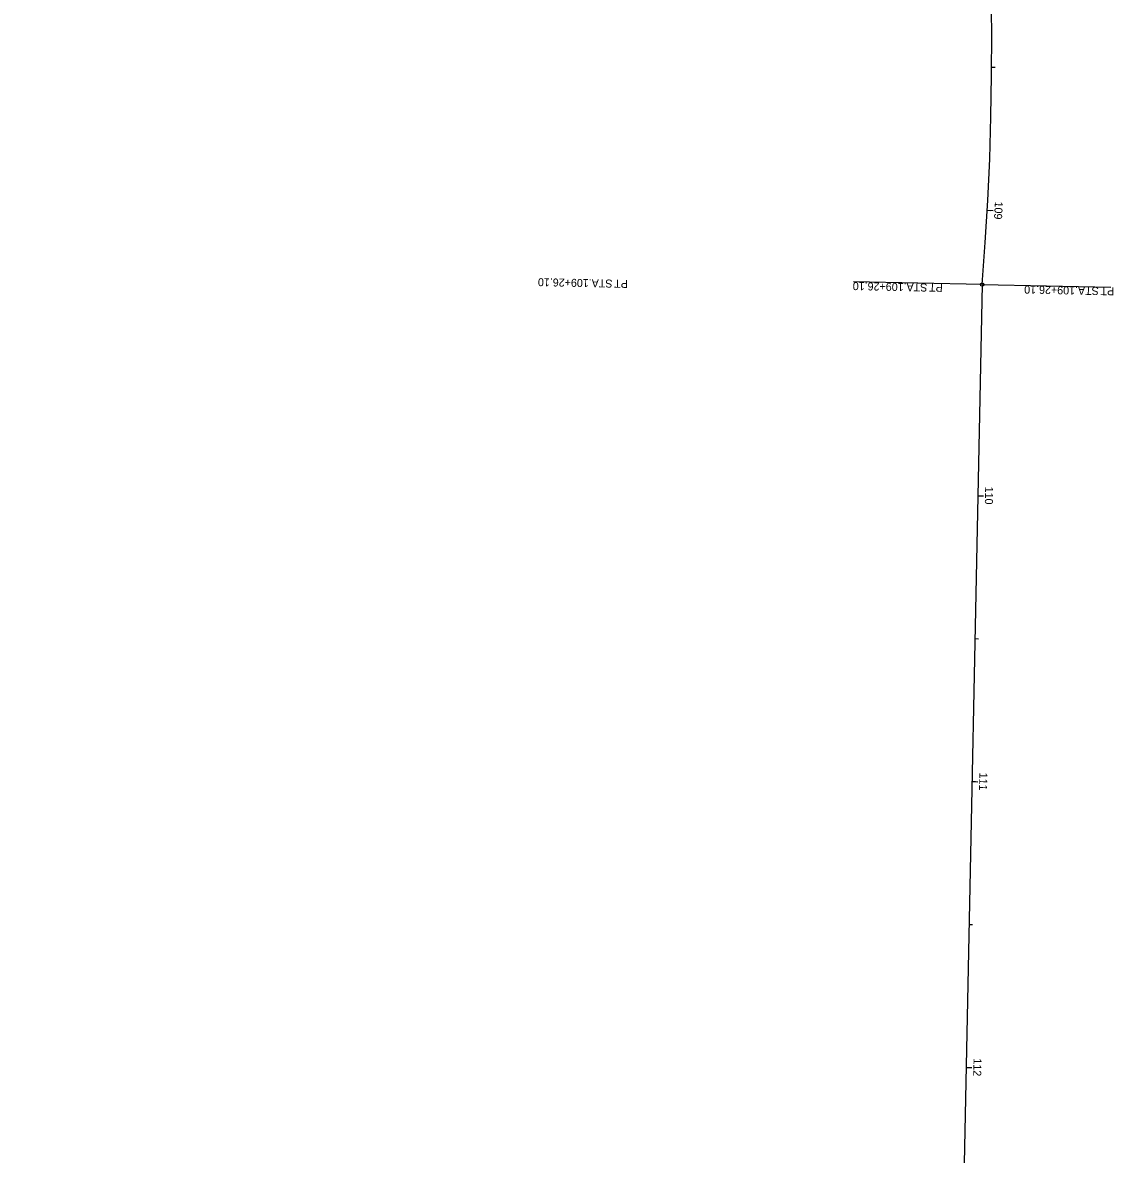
# Model space of a CAD drawing. Extents: x 1392427 to 1392809, y 435950 to 439080.
# Drawn here: x 1392427.6 to 1392809.3, y 437913.4 to 438309.3 of the extents above; entities that cross this region are included whole.
import ezdxf

# ---------------------------------------------------------------- set-up
doc = ezdxf.new("R2010")
doc.units = 0
for name, color, linetype in [('Default', 7, 'Continuous'), ('PV_X_Curb', 7, 'Continuous'), ('RD_X_Cells', 7, 'Continuous'), ('RW_X_CL', 7, 'Continuous'), ('RW_X_CL_100_Cardinal_Points', 7, 'Continuous'), ('RW_X_CL_100_Stations', 7, 'Continuous'), ('SV_X_Mon_Cells_Found', 7, 'Continuous'), ('UT_X_Gas_Cells', 7, 'Continuous'), ('UT_X_Telecom_Cells', 7, 'Continuous'), ('VG_X_Shrub_Line_Lt', 7, 'Continuous')]:
    doc.layers.add(name, color=color, linetype=linetype)

msp = doc.modelspace()

# ---------------------------------------------------------------- linework, layer by layer
at = {"layer": 'Default'}
msp.add_line((1392763.4, 438217.67), (1392717.33, 435953.92), dxfattribs=at)
msp.add_arc((1391776.54, 438298.83), 990.19, 355.29887, 48.88602, dxfattribs=at)
at = {"layer": 'PV_X_Curb'}
for p, q in [((1392765.2, 438243.71), (1392766.4, 438243.64)), ((1392761.9, 438143.79), (1392763.9, 438143.75)), ((1392759.86, 438043.81), (1392761.06, 438043.78)), ((1392757.83, 437943.83), (1392759.03, 437943.8))]:
    msp.add_line(p, q, dxfattribs=at)
at = {"layer": 'RD_X_Cells'}
msp.add_line((1392761.9, 438143.79), (1392763.9, 438143.75), dxfattribs=at)
at = {"layer": 'RW_X_CL'}
msp.add_line((1392763.4, 438217.67), (1392717.33, 435953.92), dxfattribs=at)
msp.add_line((1392763.4, 438217.67), (1392717.33, 435953.92), dxfattribs=at)
msp.add_arc((1391776.54, 438298.83), 990.19, 355.29887, 48.88602, dxfattribs=at)
msp.add_arc((1391776.54, 438298.83), 990.19, 355.29887, 48.88602, dxfattribs=at)
at = {"layer": 'RW_X_CL_100_Cardinal_Points'}
msp.add_line((1392763.4, 438217.67), (1392718.41, 438218.59), dxfattribs=at)
msp.add_circle((1392763.4, 438217.67), 0.6, dxfattribs=at)
at = {"layer": 'RW_X_CL_100_Stations'}
for p, q in [((1392766.72, 438293.68), (1392767.92, 438293.68)), ((1392765.2, 438243.71), (1392767.19, 438243.6)), ((1392761.9, 438143.79), (1392763.9, 438143.75)), ((1392760.88, 438093.8), (1392762.08, 438093.77)), ((1392759.86, 438043.81), (1392761.86, 438043.77)), ((1392758.85, 437993.82), (1392760.05, 437993.79)), ((1392757.83, 437943.83), (1392759.83, 437943.79))]:
    msp.add_line(p, q, dxfattribs=at)
at = {"layer": 'SV_X_Mon_Cells_Found'}
for p, q in [((1392765.2, 438243.71), (1392766.4, 438243.64)), ((1392761.9, 438143.79), (1392763.9, 438143.75)), ((1392759.86, 438043.81), (1392761.06, 438043.78)), ((1392757.83, 437943.83), (1392759.03, 437943.8))]:
    msp.add_line(p, q, dxfattribs=at)
at = {"layer": 'UT_X_Gas_Cells'}
msp.add_line((1392763.4, 438217.67), (1392718.41, 438218.59), dxfattribs=at)
msp.add_circle((1392763.4, 438217.67), 0.6, dxfattribs=at)
at = {"layer": 'UT_X_Telecom_Cells'}
msp.add_line((1392763.4, 438217.67), (1392718.41, 438218.59), dxfattribs=at)
msp.add_circle((1392763.4, 438217.67), 0.6, dxfattribs=at)
at = {"layer": 'VG_X_Shrub_Line_Lt'}
msp.add_line((1392763.4, 438217.67), (1392808.39, 438216.76), dxfattribs=at)
msp.add_circle((1392763.4, 438217.67), 0.6, dxfattribs=at)

# ---------------------------------------------------------------- texts
at = {"layer": 'PV_X_Curb'}
msp.add_text('110', height=2.8, rotation=268.834, dxfattribs=at).set_placement((1392764.46, 438147))
at = {"layer": 'RD_X_Cells'}
msp.add_text('110', height=2.8, rotation=268.834, dxfattribs=at).set_placement((1392764.46, 438147))
at = {"layer": 'RW_X_CL_100_Cardinal_Points'}
for s, p in [('109+26.10', (1392735.94, 438218.19)), (' STA. ', (1392745.27, 438218)), ('PT', (1392749.62, 438217.92))]:
    msp.add_text(s, height=2.8, rotation=178.834, dxfattribs=at).set_placement(p)
at = {"layer": 'RW_X_CL_100_Stations'}
for s, rotation, p in [('109', 266.8092, (1392767.87, 438246.79)), ('110', 268.834, (1392764.46, 438147)), ('111', 268.834, (1392762.43, 438046.98)), ('112', 268.834, (1392760.39, 437946.99))]:
    msp.add_text(s, height=2.8, rotation=rotation, dxfattribs=at).set_placement(p)
at = {"layer": 'SV_X_Mon_Cells_Found'}
msp.add_text('110', height=2.8, rotation=268.834, dxfattribs=at).set_placement((1392764.46, 438147))
at = {"layer": 'UT_X_Gas_Cells'}
for s, p in [('109+26.10', (1392625.78, 438219.57)), (' STA. ', (1392635.1, 438219.38)), ('PT', (1392639.45, 438219.29))]:
    msp.add_text(s, height=2.8, rotation=178.834, dxfattribs=at).set_placement(p)
at = {"layer": 'UT_X_Telecom_Cells'}
for s, p in [('109+26.10', (1392625.78, 438219.57)), (' STA. ', (1392635.1, 438219.38)), ('PT', (1392639.45, 438219.29))]:
    msp.add_text(s, height=2.8, rotation=178.834, dxfattribs=at).set_placement(p)
at = {"layer": 'VG_X_Shrub_Line_Lt'}
for s, p in [('109+26.10', (1392795.93, 438216.97)), (' STA. ', (1392805.25, 438216.78)), ('PT', (1392809.6, 438216.69))]:
    msp.add_text(s, height=2.8, rotation=178.834, dxfattribs=at).set_placement(p)

doc.saveas('drawing.dxf')
